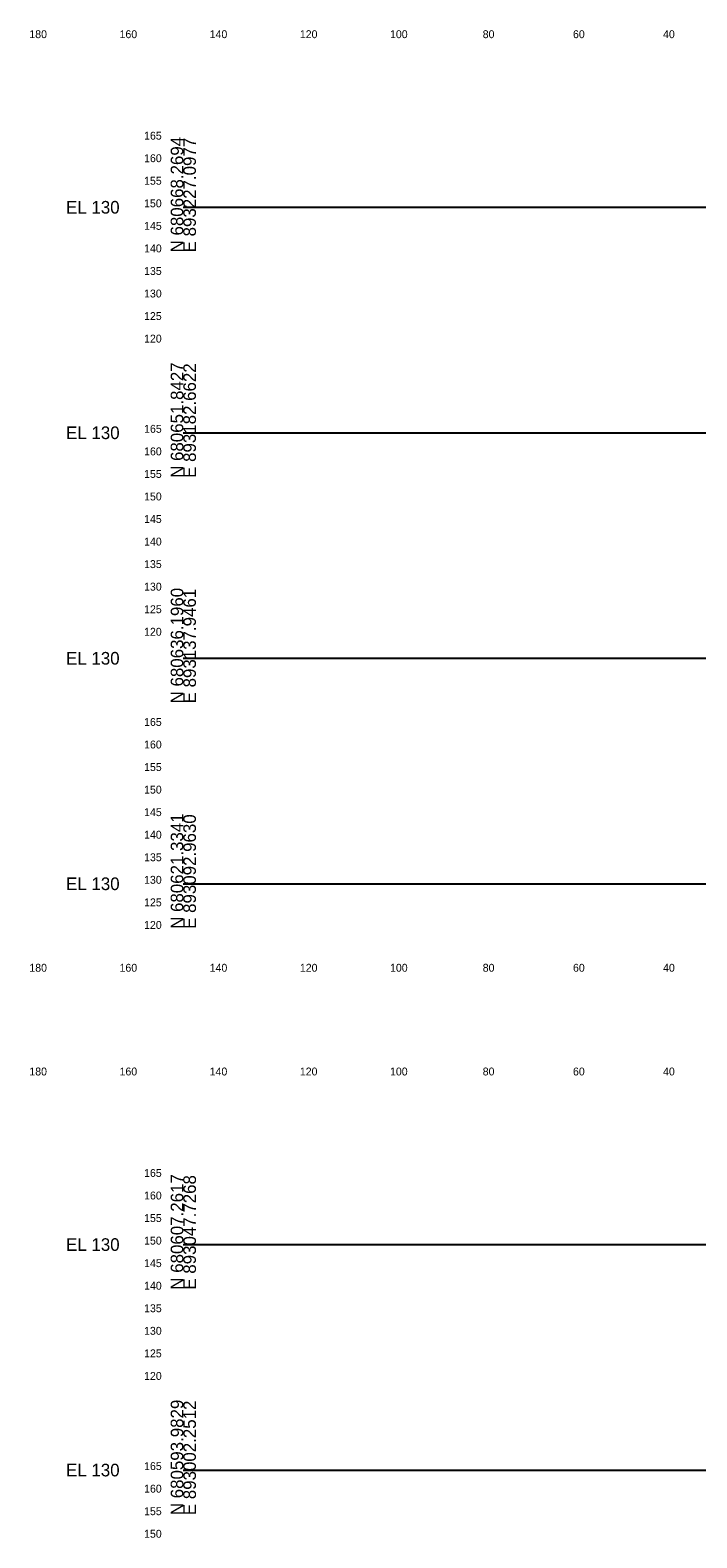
# Model space of a CAD drawing. Extents: x 21059 to 22955, y 6470 to 17494.
# Drawn here: x 21460.9 to 21608.7, y 7499.8 to 7834.1 of the extents above; entities that cross this region are included whole.
import ezdxf

# ---------------------------------------------------------------- set-up
doc = ezdxf.new("R2010")
doc.units = 0
for name, color, linetype in [('Draft_XS_Grid', 7, 'Continuous'), ('Draft_XS_Text', 7, 'Continuous'), ('DTM CONTOURS_MAJOR', 7, 'Continuous')]:
    doc.layers.add(name, color=color, linetype=linetype)

msp = doc.modelspace()

# ---------------------------------------------------------------- linework, layer by layer
at = {"layer": 'DTM CONTOURS_MAJOR'}
for p, q in [((21494.84, 7794.84), (21644.84, 7794.84)), ((21494.84, 7744.84), (21644.84, 7744.84)), ((21494.84, 7694.84), (21644.84, 7694.84)), ((21494.84, 7644.84), (21644.84, 7644.84)), ((21494.84, 7564.84), (21644.84, 7564.84)), ((21494.84, 7514.84), (21644.84, 7514.84))]:
    msp.add_line(p, q, dxfattribs=at)

# ---------------------------------------------------------------- texts
at = {"layer": 'Draft_XS_Grid'}
for s, p in [('  165  ', (21484.84, 7809.84)), ('  160  ', (21484.84, 7804.84)), ('  155  ', (21484.84, 7799.84)), ('  150  ', (21484.84, 7794.84)), ('  145  ', (21484.84, 7789.84)), ('  140  ', (21484.84, 7784.84)), ('  135  ', (21484.84, 7779.84)), ('  130  ', (21484.84, 7774.84)), ('  125  ', (21484.84, 7769.84)), ('  120  ', (21484.84, 7764.84)), ('  165  ', (21484.84, 7744.84)), ('  160  ', (21484.84, 7739.84)), ('  155  ', (21484.84, 7734.84)), ('  150  ', (21484.84, 7729.84)), ('  145  ', (21484.84, 7724.84)), ('  140  ', (21484.84, 7719.84)), ('  135  ', (21484.84, 7714.84)), ('  130  ', (21484.84, 7709.84)), ('  125  ', (21484.84, 7704.84)), ('  120  ', (21484.84, 7699.84)), ('  165  ', (21484.84, 7679.84)), ('  160  ', (21484.84, 7674.84)), ('  155  ', (21484.84, 7669.84)), ('  150  ', (21484.84, 7664.84)), ('  145  ', (21484.84, 7659.84)), ('  140  ', (21484.84, 7654.84)), ('  135  ', (21484.84, 7649.84)), ('  130  ', (21484.84, 7644.84)), ('  125  ', (21484.84, 7639.84)), ('  120  ', (21484.84, 7634.84)), ('  165  ', (21484.84, 7579.84)), ('  160  ', (21484.84, 7574.84)), ('  155  ', (21484.84, 7569.84)), ('  150  ', (21484.84, 7564.84)), ('  145  ', (21484.84, 7559.84)), ('  140  ', (21484.84, 7554.84)), ('  135  ', (21484.84, 7549.84)), ('  130  ', (21484.84, 7544.84)), ('  125  ', (21484.84, 7539.84)), ('  120  ', (21484.84, 7534.84)), ('  165  ', (21484.84, 7514.84)), ('  160  ', (21484.84, 7509.84)), ('  155  ', (21484.84, 7504.84)), ('  150  ', (21484.84, 7499.84))]:
    msp.add_text(s, height=1.75, dxfattribs=at).set_placement(p)
at = {"layer": 'Draft_XS_Text'}
for s, p in [('  180  ', (21459.39, 7832.34)), ('  160  ', (21479.4, 7832.34)), ('  140  ', (21499.39, 7832.34)), ('  120  ', (21519.39, 7832.34)), ('  100  ', (21539.39, 7832.34)), ('  80  ', (21559.95, 7832.34)), ('  60  ', (21579.97, 7832.34)), ('  40  ', (21599.95, 7832.34)), ('  180  ', (21459.39, 7625.34)), ('  160  ', (21479.4, 7625.34)), ('  140  ', (21499.39, 7625.34)), ('  120  ', (21519.39, 7625.34)), ('  100  ', (21539.39, 7625.34)), ('  80  ', (21559.95, 7625.34)), ('  60  ', (21579.97, 7625.34)), ('  40  ', (21599.95, 7625.34)), ('  180  ', (21459.39, 7602.34)), ('  160  ', (21479.4, 7602.34)), ('  140  ', (21499.39, 7602.34)), ('  120  ', (21519.39, 7602.34)), ('  100  ', (21539.39, 7602.34)), ('  80  ', (21559.95, 7602.34)), ('  60  ', (21579.97, 7602.34)), ('  40  ', (21599.95, 7602.34))]:
    msp.add_text(s, height=1.75, dxfattribs=at).set_placement(p)
at = {"layer": 'DTM CONTOURS_MAJOR'}
for s, p in [('N 680668.2694', (21494.84, 7784.84)), ('E 893227.0977', (21497.64, 7784.84)), ('N 680651.8427', (21494.84, 7734.84)), ('E 893182.6622', (21497.64, 7734.84)), ('N 680636.1960', (21494.84, 7684.84)), ('E 893137.9461', (21497.64, 7684.84)), ('N 680621.3341', (21494.84, 7634.84)), ('E 893092.9630', (21497.64, 7634.84)), ('N 680607.2617', (21494.84, 7554.84)), ('E 893047.7268', (21497.64, 7554.84)), ('N 680593.9829', (21494.84, 7504.84)), ('E 893002.2512', (21497.64, 7504.84))]:
    msp.add_text(s, height=2.8, rotation=90, dxfattribs=at).set_placement(p)
for p in [(21468.84, 7793.44), (21468.84, 7743.44), (21468.84, 7693.44), (21468.84, 7643.44), (21468.84, 7563.44), (21468.84, 7513.44)]:
    msp.add_text('EL 130', height=2.8, dxfattribs=at).set_placement(p)

doc.saveas('drawing.dxf')
